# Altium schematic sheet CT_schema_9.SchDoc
size 147 x 119 mm
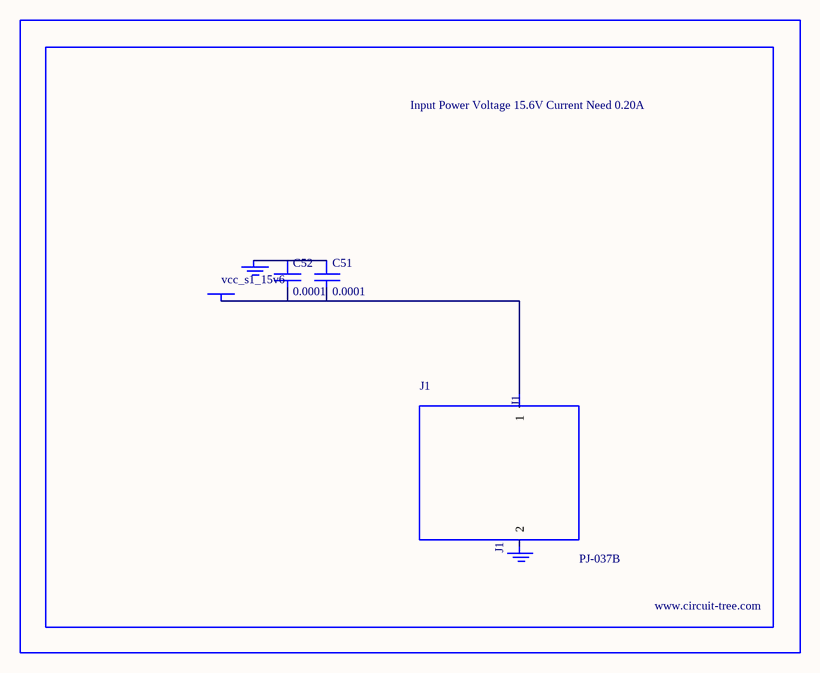
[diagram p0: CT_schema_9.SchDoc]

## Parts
BORDER8  (no value)
C51  0.0001  [EXV-9H]
C52  0.0001  [EXV-9H]
GND_INSTANCE_8_0  (no value)
GND_INSTANCE_8_1  (no value)
J1  PJ-037B  [PJ-037B_PACKAGE]
POWER_INSTANCE_8_0  vcc_s1_15v6

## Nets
NetC51_1: C51.1 C52.1 GND_INSTANCE_8_0.0(GND)
NetC51_2: C51.2 C52.2 J1.1 POWER_INSTANCE_8_0.0(PWR)

Not connected (* = marked no-connect by the designer): GND_INSTANCE_8_1 0(GND); J1 2

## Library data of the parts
BORDER8 = BORDER_PAGE8
C51 C52 = EDK107M035A9HAA
GND_INSTANCE_8_0 GND_INSTANCE_8_1 = GND
POWER_INSTANCE_8_0 = PWR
